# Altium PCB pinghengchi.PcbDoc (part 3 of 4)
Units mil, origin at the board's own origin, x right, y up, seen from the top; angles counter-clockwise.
Board outline 3880 x 3935 mil, 2 copper layers (Top Layer, Bottom Layer); 79 components, 147 nets, 520 pads, 52 vias.
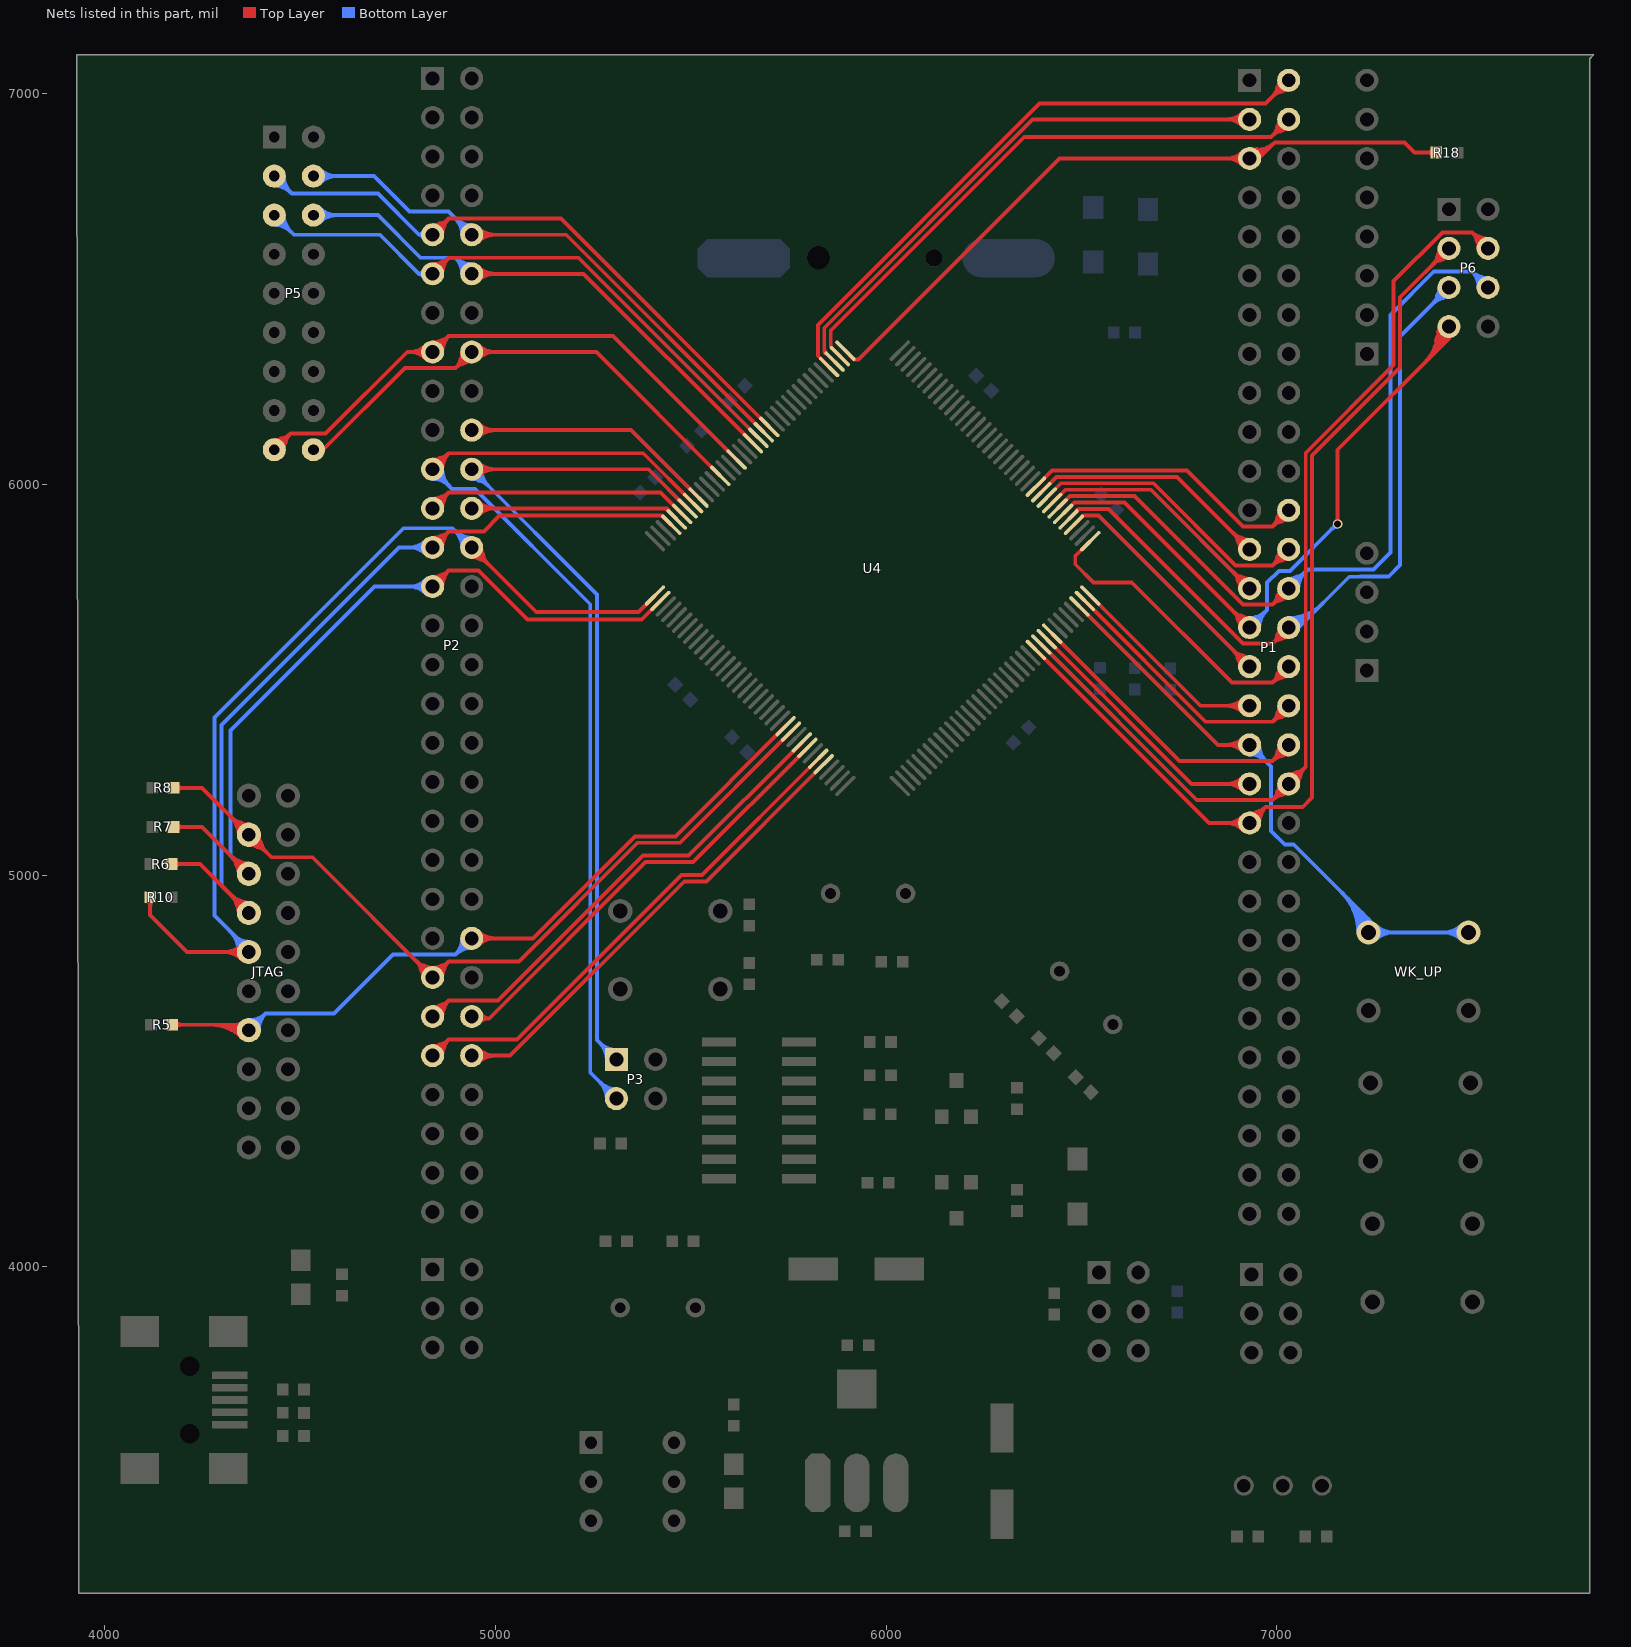
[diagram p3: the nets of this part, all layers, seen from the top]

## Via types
v1: diameter 24, hole 18, Top Layer to Bottom Layer, 42 vias
v2: diameter 24, hole 16, Top Layer to Bottom Layer, 4 vias
v3: diameter 125.98, hole 118.11, Top Layer to Bottom Layer, 4 vias
v4: diameter 30, hole 20, Top Layer to Bottom Layer, 2 vias

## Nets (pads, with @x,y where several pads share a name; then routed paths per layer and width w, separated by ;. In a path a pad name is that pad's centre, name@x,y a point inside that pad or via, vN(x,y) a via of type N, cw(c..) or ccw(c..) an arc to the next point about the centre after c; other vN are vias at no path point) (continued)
OV_RRST: P2.11 P5.5 U4.89 | length 2239.4
  Top Layer w10: P2.11@4834.67,6541.26 cw(c4872.93,6532.2) 4863.31,6570.32 ; P2.11@4840,6540 4881.03,6581.03 ; P2.11@4841.26,6534.67 ccw(c4832.2,6572.93) 4870.32,6563.31 ; U4.89@5673.33,6120.57 5212.88,6581.03 4881.03,6581.03 ; 4864.3,6564.3 ccw(c4887.9,6540.7) 4854.53,6540.21 cw(c4887.9,6540.7) 4864.3,6564.3 ; 4864.3,6564.3 cw(c4840.7,6587.9) 4840.21,6554.53 ccw(c4840.7,6587.9) 4864.3,6564.3 ; 4881.03,6581.03 ccw(c4920.87,6541.18) 4864.52,6540.36 cw(c4920.87,6541.18) 4881.03,6581.03 ; 4881.03,6581.03 cw(c4841.18,6620.87) 4840.36,6564.52 ccw(c4841.18,6620.87) 4881.03,6581.03
  Bottom Layer w10: P5.5@4435,6690 4485,6640 4705,6640 4805,6540 ; P2.11@4840,6540 4805,6540 ; 4459.8,6665.2 ccw(c4435,6640.4) 4435,6675.47 cw(c4435,6640.4) 4459.8,6665.2 ; 4459.8,6665.2 cw(c4484.6,6690) 4449.53,6690 ccw(c4484.6,6690) 4459.8,6665.2 ; 4476.87,6648.13 ccw(c4435,6606.26) 4435,6665.47 cw(c4435,6606.26) 4476.87,6648.13 ; 4476.87,6648.13 cw(c4518.74,6690) 4459.53,6690 ccw(c4518.74,6690) 4476.87,6648.13 ; 4805,6540 ccw(c4805,6552.71) 4816.94,6548.37 cw(c4805,6552.71) 4805,6540 ; 4805,6540 cw(c4805,6527.29) 4816.94,6531.63 ccw(c4805,6527.29) 4805,6540
OV_SCL: P2.10 P5.4 U4.88 | length 2312.4
  Top Layer w10: P2.10@4940,6640 5181.74,6640 U4.88@5687.25,6134.49 ; 4975.07,6640 ccw(c4975.07,6604.93) 4950.27,6629.73 cw(c4975.07,6604.93) 4975.07,6640 ; 4975.07,6640 cw(c4975.07,6675.07) 4950.27,6650.27 ccw(c4975.07,6675.07) 4975.07,6640 ; 4999.21,6640 ccw(c4999.21,6580.79) 4957.34,6622.66 cw(c4999.21,6580.79) 4999.21,6640 ; 4999.21,6640 cw(c4999.21,6699.21) 4957.34,6657.34 ccw(c4999.21,6699.21) 4999.21,6640
  Bottom Layer w10: P5.4@4535,6790 4690,6790 4781.03,6698.97 4881.03,6698.97 P2.10@4940,6640 ; 4570.07,6790 ccw(c4570.07,6754.93) 4545.27,6779.73 cw(c4570.07,6754.93) 4570.07,6790 ; 4570.07,6790 cw(c4570.07,6825.07) 4545.27,6800.27 ccw(c4570.07,6825.07) 4570.07,6790 ; 4594.21,6790 ccw(c4594.21,6730.79) 4552.34,6772.66 cw(c4594.21,6730.79) 4594.21,6790 ; 4594.21,6790 cw(c4594.21,6849.21) 4552.34,6807.34 ccw(c4594.21,6849.21) 4594.21,6790 ; 4898.13,6681.87 ccw(c4940,6723.74) 4940,6664.53 cw(c4940,6723.74) 4898.13,6681.87 ; 4898.13,6681.87 cw(c4856.26,6640) 4915.47,6640 ccw(c4856.26,6640) 4898.13,6681.87 ; 4915.2,6664.8 ccw(c4940,6689.6) 4940,6654.53 cw(c4940,6689.6) 4915.2,6664.8 ; 4915.2,6664.8 cw(c4890.4,6640) 4925.47,6640 ccw(c4890.4,6640) 4915.2,6664.8
OV_SDA: P2.12 P5.6 U4.90 | length 2245.6
  Top Layer w10: P2.12@4940,6540 5226.07,6540 U4.90@5659.41,6106.66 ; 4975.07,6540 ccw(c4975.07,6504.93) 4950.27,6529.73 cw(c4975.07,6504.93) 4975.07,6540 ; 4975.07,6540 cw(c4975.07,6575.07) 4950.27,6550.27 ccw(c4975.07,6575.07) 4975.07,6540 ; 4999.21,6540 ccw(c4999.21,6480.79) 4957.34,6522.66 cw(c4999.21,6480.79) 4999.21,6540 ; 4999.21,6540 cw(c4999.21,6599.21) 4957.34,6557.34 ccw(c4999.21,6599.21) 4999.21,6540
  Bottom Layer w10: P5.6@4535,6690 4700,6690 4808.97,6581.03 4898.97,6581.03 ; P2.12@4940,6540 4898.97,6581.03 ; 4570.07,6690 ccw(c4570.07,6654.93) 4545.27,6679.73 cw(c4570.07,6654.93) 4570.07,6690 ; 4570.07,6690 cw(c4570.07,6725.07) 4545.27,6700.27 ccw(c4570.07,6725.07) 4570.07,6690 ; 4594.21,6690 ccw(c4594.21,6630.79) 4552.34,6672.66 cw(c4594.21,6630.79) 4594.21,6690 ; 4594.21,6690 cw(c4594.21,6749.21) 4552.34,6707.34 ccw(c4594.21,6749.21) 4594.21,6690 ; 4898.97,6581.03 ccw(c4938.82,6620.87) 4939.64,6564.52 cw(c4938.82,6620.87) 4898.97,6581.03 ; 4898.97,6581.03 cw(c4859.13,6541.18) 4915.48,6540.36 ccw(c4859.13,6541.18) 4898.97,6581.03 ; 4915.7,6564.3 ccw(c4939.3,6587.9) 4939.79,6554.53 cw(c4939.3,6587.9) 4915.7,6564.3 ; 4915.7,6564.3 cw(c4892.1,6540.7) 4925.47,6540.21 ccw(c4892.1,6540.7) 4915.7,6564.3
OV_VSYNC: P2.15 P5.17 U4.93 | length 2476.2
  Top Layer w10: P5.17@4429.67,6091.26 cw(c4467.93,6082.2) 4458.31,6120.32 ; P5.17@4435,6090 4476.03,6131.03 ; P5.17@4436.26,6084.67 ccw(c4427.2,6122.93) 4465.32,6113.31 ; P2.15@4834.67,6341.26 cw(c4872.93,6332.2) 4863.31,6370.32 ; P2.15@4841.26,6334.67 ccw(c4832.2,6372.93) 4870.32,6363.31 ; U4.93@5617.65,6064.9 5301.52,6381.03 4881.03,6381.03 ; 4459.3,6114.3 ccw(c4482.9,6090.7) 4449.53,6090.21 cw(c4482.9,6090.7) 4459.3,6114.3 ; 4459.3,6114.3 cw(c4435.7,6137.9) 4435.21,6104.53 ccw(c4435.7,6137.9) 4459.3,6114.3 ; 4476.03,6131.03 ccw(c4515.87,6091.18) 4459.52,6090.36 cw(c4515.87,6091.18) 4476.03,6131.03 ; 4476.03,6131.03 cw(c4436.18,6170.87) 4435.36,6114.52 ccw(c4436.18,6170.87) 4476.03,6131.03 ; 4476.03,6131.03 4566.03,6131.03 4775,6340 P2.15@4840,6340 4881.03,6381.03 ; 4780.79,6340 ccw(c4780.79,6399.21) 4822.66,6357.34 cw(c4780.79,6399.21) 4780.79,6340 ; 4780.79,6340 cw(c4780.79,6280.79) 4822.66,6322.66 ccw(c4780.79,6280.79) 4780.79,6340 ; 4804.93,6340 ccw(c4804.93,6375.07) 4829.73,6350.27 cw(c4804.93,6375.07) 4804.93,6340 ; 4804.93,6340 cw(c4804.93,6304.93) 4829.73,6329.73 ccw(c4804.93,6304.93) 4804.93,6340 ; 4864.3,6364.3 ccw(c4887.9,6340.7) 4854.53,6340.21 cw(c4887.9,6340.7) 4864.3,6364.3 ; 4864.3,6364.3 cw(c4840.7,6387.9) 4840.21,6354.53 ccw(c4840.7,6387.9) 4864.3,6364.3 ; 4881.03,6381.03 ccw(c4920.87,6341.18) 4864.52,6340.36 cw(c4920.87,6341.18) 4881.03,6381.03 ; 4881.03,6381.03 cw(c4841.18,6420.87) 4840.36,6364.52 ccw(c4841.18,6420.87) 4881.03,6381.03
OV_WEN: P2.16 P5.18 U4.96 | length 1944.8
  Top Layer w10: P5.18@4535,6090 4560,6090 4768.97,6298.97 4898.97,6298.97 ; 4909.68,6316.69 cw(c4947.8,6307.07) P2.16@4938.74,6345.33 ; 4916.69,6309.68 ccw(c4907.07,6347.8) P2.16@4945.33,6338.74 ; U4.96@5575.89,6023.14 5259.03,6340 P2.16@4940,6340 4898.97,6298.97 ; 4898.97,6298.97 ccw(c4859.13,6338.82) 4915.48,6339.64 cw(c4859.13,6338.82) 4898.97,6298.97 ; 4898.97,6298.97 cw(c4938.82,6259.13) 4939.64,6315.48 ccw(c4938.82,6259.13) 4898.97,6298.97 ; 4915.7,6315.7 ccw(c4892.1,6339.3) 4925.47,6339.79 cw(c4892.1,6339.3) 4915.7,6315.7 ; 4915.7,6315.7 cw(c4939.3,6292.1) 4939.79,6325.47 ccw(c4939.3,6292.1) 4915.7,6315.7 ; 4975.07,6340 ccw(c4975.07,6304.93) 4950.27,6329.73 cw(c4975.07,6304.93) 4975.07,6340 ; 4975.07,6340 cw(c4975.07,6375.07) 4950.27,6350.27 ccw(c4975.07,6375.07) 4975.07,6340 ; 4999.21,6340 ccw(c4999.21,6280.79) 4957.34,6322.66 cw(c4999.21,6280.79) 4999.21,6340 ; 4999.21,6340 cw(c4999.21,6399.21) 4957.34,6357.34 ccw(c4999.21,6399.21) 4999.21,6340
OV_WRST: P2.9 P5.3 U4.87 | length 2297.2
  Top Layer w10: P2.9@4834.67,6641.26 cw(c4872.93,6632.2) 4863.31,6670.32 ; P2.9@4840,6640 4881.03,6681.03 ; P2.9@4841.26,6634.67 ccw(c4832.2,6672.93) 4870.32,6663.31 ; U4.87@5701.17,6148.41 5168.55,6681.03 4881.03,6681.03 ; 4864.3,6664.3 ccw(c4887.9,6640.7) 4854.53,6640.21 cw(c4887.9,6640.7) 4864.3,6664.3 ; 4864.3,6664.3 cw(c4840.7,6687.9) 4840.21,6654.53 ccw(c4840.7,6687.9) 4864.3,6664.3 ; 4881.03,6681.03 ccw(c4920.87,6641.18) 4864.52,6640.36 cw(c4920.87,6641.18) 4881.03,6681.03 ; 4881.03,6681.03 cw(c4841.18,6720.87) 4840.36,6664.52 ccw(c4841.18,6720.87) 4881.03,6681.03
  Bottom Layer w10: P5.3@4435,6790 4480,6745 4700,6745 4805,6640 ; P2.9@4840,6640 4805,6640 ; 4459.8,6765.2 ccw(c4435,6740.4) 4435,6775.47 cw(c4435,6740.4) 4459.8,6765.2 ; 4459.8,6765.2 cw(c4484.6,6790) 4449.53,6790 ccw(c4484.6,6790) 4459.8,6765.2 ; 4476.87,6748.13 ccw(c4435,6706.26) 4435,6765.47 cw(c4435,6706.26) 4476.87,6748.13 ; 4476.87,6748.13 cw(c4518.74,6790) 4459.53,6790 ccw(c4518.74,6790) 4476.87,6748.13 ; 4805,6640 ccw(c4805,6652.71) 4816.94,6648.37 cw(c4805,6652.71) 4805,6640 ; 4805,6640 cw(c4805,6627.29) 4816.94,6631.63 ccw(c4805,6627.29) 4805,6640
PA0: P1.35 U4.34 WK_UP.2 | length 3674.7
  Top Layer w10: U4.34@6494.57,5689.07 6848.65,5335 P1.35@6930,5335 ; 6870.79,5335 ccw(c6870.79,5394.21) 6912.66,5352.34 cw(c6870.79,5394.21) 6870.79,5335 ; 6870.79,5335 cw(c6870.79,5275.79) 6912.66,5317.66 ccw(c6870.79,5275.79) 6870.79,5335 ; 6894.93,5335 ccw(c6894.93,5370.07) 6919.73,5345.27 cw(c6894.93,5370.07) 6894.93,5335 ; 6894.93,5335 cw(c6894.93,5299.93) 6919.73,5324.73 ccw(c6894.93,5299.93) 6894.93,5335
  Bottom Layer w10: P1.35@6930,5335 6985,5280 6985,5115 7020,5080 7043.02,5080 7234.09,4888.93 ; 7201.24,4919.14 ccw(c7277.09,4939.07) WK_UP.2@7241.38,4869.24 ; 7206.92,4897.51 ccw(c7263.43,4912.36) WK_UP.2@7236.83,4860.34 ; WK_UP.2@7211.58,4868 ccw(c7174.35,4889.49) 7215.87,4900.62 ; 7217.59,4894.21 ccw(c7252.02,4903.44) WK_UP.2@7239.65,4870.01 ; WK_UP.2@7490,4855 WK_UP.2@7234.09,4855 7234.09,4888.93 ; 6954.8,5310.2 ccw(c6930,5285.4) 6930,5320.47 cw(c6930,5285.4) 6954.8,5310.2 ; 6954.8,5310.2 cw(c6979.6,5335) 6944.53,5335 ccw(c6979.6,5335) 6954.8,5310.2 ; 6971.87,5293.13 ccw(c6930,5251.26) 6930,5310.47 cw(c6930,5251.26) 6971.87,5293.13 ; 6971.87,5293.13 cw(c7013.74,5335) 6954.53,5335 ccw(c7013.74,5335) 6971.87,5293.13 ; 7234.09,4888.93 ccw(c7243.23,4888.93) 7240.85,4880.11 cw(c7243.23,4888.93) 7234.09,4888.93 ; 7234.09,4888.93 cw(c7224.96,4888.93) 7227.33,4880.11 ccw(c7224.96,4888.93) 7234.09,4888.93 ; 7272.72,4855 ccw(c7272.72,4816.37) 7245.41,4843.69 cw(c7272.72,4816.37) 7272.72,4855 ; 7272.72,4855 cw(c7272.72,4893.63) 7245.41,4866.31 ccw(c7272.72,4893.63) 7272.72,4855 ; 7296.86,4855 ccw(c7296.86,4792.23) 7252.48,4836.62 cw(c7296.86,4792.23) 7296.86,4855 ; 7296.86,4855 cw(c7296.86,4917.77) 7252.48,4873.38 ccw(c7296.86,4917.77) 7296.86,4855 ; 7427.23,4855 ccw(c7427.23,4917.77) 7471.62,4873.38 cw(c7427.23,4917.77) 7427.23,4855 ; 7427.23,4855 cw(c7427.23,4792.23) 7471.62,4836.62 ccw(c7427.23,4792.23) 7427.23,4855 ; 7451.37,4855 ccw(c7451.37,4893.63) 7478.69,4866.31 cw(c7451.37,4893.63) 7451.37,4855 ; 7451.37,4855 cw(c7451.37,4816.37) 7478.69,4843.69 ccw(c7451.37,4816.37) 7451.37,4855 ; 7165.72,4957.3 cw(c7063.42,4855) 7208.09,4855 ccw(c7063.42,4855) 7165.72,4957.3 ; 7182.79,4940.23 cw(c7097.56,4855) 7218.09,4855 ccw(c7097.56,4855) 7182.79,4940.23 ; 7199.86,4923.16 cw(c7131.7,4855) 7228.09,4855 ccw(c7131.7,4855) 7199.86,4923.16 ; 7216.93,4906.09 cw(c7165.84,4855) 7238.09,4855 ccw(c7165.84,4855) 7216.93,4906.09 ; 7234,4889.02 cw(c7199.98,4855) 7248.09,4855 ccw(c7199.98,4855) 7234,4889.02
PA1: P1.34 U4.35 | length 1039.4
  Top Layer w10: U4.35@6508.49,5702.99 6817.51,5393.97 6988.97,5393.97 ; 6999.68,5411.69 cw(c7037.8,5402.07) P1.34@7028.74,5440.33 ; 7006.69,5404.68 ccw(c6997.07,5442.8) P1.34@7035.33,5433.74 ; P1.34@7030,5435 6988.97,5393.97 ; 6988.97,5393.97 ccw(c6949.13,5433.82) 7005.48,5434.64 cw(c6949.13,5433.82) 6988.97,5393.97 ; 6988.97,5393.97 cw(c7028.82,5354.13) 7029.64,5410.48 ccw(c7028.82,5354.13) 6988.97,5393.97 ; 7005.7,5410.7 ccw(c6982.1,5434.3) 7015.47,5434.79 cw(c6982.1,5434.3) 7005.7,5410.7 ; 7005.7,5410.7 cw(c7029.3,5387.1) 7029.79,5420.47 ccw(c7029.3,5387.1) 7005.7,5410.7
PA2: P1.33 U4.36 | length 820.6
  Top Layer w10: U4.36@6522.41,5716.91 6804.32,5435 P1.33@6930,5435 ; 6870.79,5435 ccw(c6870.79,5494.21) 6912.66,5452.34 cw(c6870.79,5494.21) 6870.79,5435 ; 6870.79,5435 cw(c6870.79,5375.79) 6912.66,5417.66 ccw(c6870.79,5375.79) 6870.79,5435 ; 6894.93,5435 ccw(c6894.93,5470.07) 6919.73,5445.27 cw(c6894.93,5470.07) 6894.93,5435 ; 6894.93,5435 cw(c6894.93,5399.93) 6919.73,5424.73 ccw(c6894.93,5399.93) 6894.93,5435
PA3: P1.32 U4.37 | length 1136.4
  Top Layer w10: U4.37@6522.41,5856.11 6484,5817.69 6484,5797 6531,5750 6628.52,5750 6884.55,5493.97 6988.97,5493.97 ; 6999.68,5511.69 cw(c7037.8,5502.07) P1.32@7028.74,5540.33 ; 7006.69,5504.68 ccw(c6997.07,5542.8) P1.32@7035.33,5533.74 ; P1.32@7030,5535 6988.97,5493.97 ; 6988.97,5493.97 ccw(c6949.13,5533.82) 7005.48,5534.64 cw(c6949.13,5533.82) 6988.97,5493.97 ; 6988.97,5493.97 cw(c7028.82,5454.13) 7029.64,5510.48 ccw(c7028.82,5454.13) 6988.97,5493.97 ; 7005.7,5510.7 ccw(c6982.1,5534.3) 7015.47,5534.79 cw(c6982.1,5534.3) 7005.7,5510.7 ; 7005.7,5510.7 cw(c7029.3,5487.1) 7029.79,5520.47 ccw(c7029.3,5487.1) 7005.7,5510.7
PA4: P1.31 U4.40 | length 1012.2
  Top Layer w10: U4.40@6480.65,5897.86 6504.37,5921.58 6543.42,5921.58 P1.31@6930,5535 ; 6899.48,5557.35 ccw(c6936.61,5567.3) P1.31@6928.9,5529.64 ; 6907.65,5565.52 cw(c6897.7,5528.39) P1.31@6935.36,5536.1 ; 6888.13,5576.87 ccw(c6930,5618.74) 6930,5559.53 cw(c6930,5618.74) 6888.13,5576.87 ; 6888.13,5576.87 cw(c6846.26,5535) 6905.47,5535 ccw(c6846.26,5535) 6888.13,5576.87 ; 6905.2,5559.8 ccw(c6930,5584.6) 6930,5549.53 cw(c6930,5584.6) 6905.2,5559.8 ; 6905.2,5559.8 cw(c6880.4,5535) 6915.47,5535 ccw(c6880.4,5535) 6905.2,5559.8 ; U4.40@6501.87,5919.43 cw(c6507.07,5914.23) 6507.07,5921.58 ccw(c6507.07,5914.23) U4.40@6501.87,5919.43
PA5: P1.30 P6.5 U4.41 | length 3236.1
  Top Layer w10: U4.41@6466.74,5911.78 6493.04,5938.08 ; 6999.68,5611.69 cw(c7037.8,5602.07) P1.30@7028.74,5640.33 ; 7006.69,5604.68 ccw(c6997.07,5642.8) P1.30@7035.33,5633.74 ; P1.30@7030,5635 6988.97,5593.97 ; 6493.04,5938.08 ccw(c6493.04,5932.92) 6487.88,5933.19 cw(c6493.04,5932.92) 6493.04,5938.08 ; 6493.04,5938.08 6568.89,5938.08 6913.01,5593.97 6988.97,5593.97 ; 6988.97,5593.97 ccw(c6949.13,5633.82) 7005.48,5634.64 cw(c6949.13,5633.82) 6988.97,5593.97 ; 6988.97,5593.97 cw(c7028.82,5554.13) 7029.64,5610.48 ccw(c7028.82,5554.13) 6988.97,5593.97 ; 7005.7,5610.7 ccw(c6982.1,5634.3) 7015.47,5634.79 cw(c6982.1,5634.3) 7005.7,5610.7 ; 7005.7,5610.7 cw(c7029.3,5587.1) 7029.79,5620.47 ccw(c7029.3,5587.1) 7005.7,5610.7 ; U4.41@6487.95,5933.35 cw(c6499.38,5921.92) 6499.38,5938.08 ccw(c6499.38,5921.92) U4.41@6487.95,5933.35
  Bottom Layer w10: P1.30@7030,5635 7055,5635 7185,5765 7211.98,5765 7213.01,5766.03 7286.03,5766.03 7315,5795 7315,6380 P6.5@7440,6505 ; P1.30@7034.2,5633.3 cw(c7073.3,5617.44) 7062.38,5658.2 ; P1.30@7043.46,5629.54 cw(c7096.63,5607.98) 7081.78,5663.4 ; P1.30@7044.29,5632.4 cw(c7062.49,5629.08) 7057.7,5646.95 ; 7409.48,6482.65 cw(c7446.61,6472.7) P6.5@7438.9,6510.36 ; 7398.13,6463.13 ccw(c7356.26,6505) 7415.47,6505 cw(c7356.26,6505) 7398.13,6463.13 ; 7398.13,6463.13 cw(c7440,6421.26) 7440,6480.47 ccw(c7440,6421.26) 7398.13,6463.13 ; 7415.2,6480.2 ccw(c7390.4,6505) 7425.47,6505 cw(c7390.4,6505) 7415.2,6480.2 ; 7415.2,6480.2 cw(c7440,6455.4) 7440,6490.47 ccw(c7440,6455.4) 7415.2,6480.2 ; P1.30@7030,5629.53 ccw(c7030,5676.67) 7063.34,5643.34 cw(c7030,5676.67) P1.30@7030,5629.53 ; P1.30@7030,5639.53 ccw(c7030,5710.81) 7080.41,5660.41 cw(c7030,5710.81) P1.30@7030,5639.53 ; P1.30@7030,5649.53 ccw(c7030,5744.96) 7097.48,5677.48 cw(c7030,5744.96) P1.30@7030,5649.53 ; P1.30@7030,5659.53 ccw(c7030,5779.1) 7114.55,5694.55 cw(c7030,5779.1) P1.30@7030,5659.53
PA6: P1.29 P6.7 U4.42 | length 3356.3
  Top Layer w10: U4.42@6452.82,5925.7 6481.7,5954.58 6610.42,5954.58 P1.29@6930,5635 ; 6899.48,5657.35 ccw(c6936.61,5667.3) P1.29@6928.9,5629.64 ; 6907.65,5665.52 cw(c6897.7,5628.39) P1.29@6935.36,5636.1 ; v1(7155,5900) 7155,6090 7440,6375 ; 7401.59,6345.38 cw(c7487.44,6325.39) P6.7@7442.32,6401.11 ; 7406.92,6368.27 cw(c7470.74,6353.4) P6.7@7437.2,6409.7 ; 7410.4,6348.75 cw(c7475.16,6331.39) P6.7@7446.26,6391.89 ; 7412.25,6391.16 cw(c7454.05,6381.42) P6.7@7432.08,6418.29 ; 7416.02,6369.71 cw(c7462.85,6357.17) P6.7@7441.95,6400.91 ; P6.7@7418.76,6392.74 cw(c7380.41,6370.59) 7423.18,6359.13 ; 7426.99,6373.35 cw(c7451.52,6366.78) P6.7@7444.19,6391.09 ; P6.7@7440,6405 7440,6375 ; 6888.13,5676.87 ccw(c6930,5718.74) 6930,5659.53 cw(c6930,5718.74) 6888.13,5676.87 ; 6888.13,5676.87 cw(c6846.26,5635) 6905.47,5635 ccw(c6846.26,5635) 6888.13,5676.87 ; 6905.2,5659.8 ccw(c6930,5684.6) 6930,5649.53 cw(c6930,5684.6) 6905.2,5659.8 ; 6905.2,5659.8 cw(c6880.4,5635) 6915.47,5635 ccw(c6880.4,5635) 6905.2,5659.8 ; 7155,5916.9 ccw(c7171.9,5916.9) 7159.95,5904.95 cw(c7171.9,5916.9) 7155,5916.9 ; 7155,5916.9 cw(c7138.1,5916.9) 7150.05,5904.95 ccw(c7138.1,5916.9) 7155,5916.9 ; 7440,6375 ccw(c7433.92,6375) 7435.13,6380.96 cw(c7433.92,6375) 7440,6375 ; 7440,6375 cw(c7446.08,6375) 7444.87,6380.96 ccw(c7446.08,6375) 7440,6375 ; 7376.92,6311.92 ccw(c7283.83,6405) 7415.47,6405 cw(c7283.83,6405) 7376.92,6311.92 ; 7393.99,6328.99 ccw(c7317.97,6405) 7425.47,6405 cw(c7317.97,6405) 7393.99,6328.99 ; 7411.06,6346.06 ccw(c7352.12,6405) 7435.47,6405 cw(c7352.12,6405) 7411.06,6346.06 ; 7428.13,6363.13 ccw(c7386.26,6405) 7445.47,6405 cw(c7386.26,6405) 7428.13,6363.13
  Bottom Layer w10: P1.29@6930,5635 6975,5680 6975,5750 7005,5780 7033.02,5780 v1@7155,5901.98 ; 6954.8,5659.8 ccw(c6979.6,5635) 6944.53,5635 cw(c6979.6,5635) 6954.8,5659.8 ; 6954.8,5659.8 cw(c6930,5684.6) 6930,5649.53 ccw(c6930,5684.6) 6954.8,5659.8 ; 6971.87,5676.87 ccw(c7013.74,5635) 6954.53,5635 cw(c7013.74,5635) 6971.87,5676.87 ; 6971.87,5676.87 cw(c6930,5718.74) 6930,5659.53 ccw(c6930,5718.74) 6971.87,5676.87 ; 7139.67,5886.65 cw(c7155,5871.32) 7155,5893 ccw(c7155,5871.32) 7139.67,5886.65 ; 7144.45,5891.43 ccw(c7135.88,5900) 7148,5900 cw(c7135.88,5900) 7144.45,5891.43
PA7: P1.28 P6.6 U4.43 | length 2953.8
  Top Layer w10: U4.43@6438.9,5939.62 6470.36,5971.08 6635.89,5971.08 6913.01,5693.97 6988.97,5693.97 ; 6999.68,5711.69 cw(c7037.8,5702.07) P1.28@7028.74,5740.33 ; 7006.69,5704.68 ccw(c6997.07,5742.8) P1.28@7035.33,5733.74 ; P1.28@7030,5735 6988.97,5693.97 ; 6988.97,5693.97 ccw(c6949.13,5733.82) 7005.48,5734.64 cw(c6949.13,5733.82) 6988.97,5693.97 ; 6988.97,5693.97 cw(c7028.82,5654.13) 7029.64,5710.48 ccw(c7028.82,5654.13) 6988.97,5693.97 ; 7005.7,5710.7 ccw(c6982.1,5734.3) 7015.47,5734.79 cw(c6982.1,5734.3) 7005.7,5710.7 ; 7005.7,5710.7 cw(c7029.3,5687.1) 7029.79,5720.47 ccw(c7029.3,5687.1) 7005.7,5710.7
  Bottom Layer w10: P1.28@7024.64,5736.1 cw(c7062.3,5728.39) 7052.35,5765.52 ; P1.28@7030,5735 7078.97,5783.97 7246.99,5783.97 7290,5826.98 7290,6435 7401.03,6546.03 7498.97,6546.03 ; P6.6@7540,6505 7498.97,6546.03 ; 7054.8,5759.8 ccw(c7079.6,5735) 7044.53,5735 cw(c7079.6,5735) 7054.8,5759.8 ; 7054.8,5759.8 cw(c7030,5784.6) 7030,5749.53 ccw(c7030,5784.6) 7054.8,5759.8 ; 7071.87,5776.87 ccw(c7113.74,5735) 7054.53,5735 cw(c7113.74,5735) 7071.87,5776.87 ; 7071.87,5776.87 cw(c7030,5818.74) 7030,5759.53 ccw(c7030,5818.74) 7071.87,5776.87 ; 7498.97,6546.03 ccw(c7538.82,6585.87) 7539.64,6529.52 cw(c7538.82,6585.87) 7498.97,6546.03 ; 7498.97,6546.03 cw(c7459.13,6506.18) 7515.48,6505.36 ccw(c7459.13,6506.18) 7498.97,6546.03 ; 7515.7,6529.3 ccw(c7539.3,6552.9) 7539.79,6519.53 cw(c7539.3,6552.9) 7515.7,6529.3 ; 7515.7,6529.3 cw(c7492.1,6505.7) 7525.47,6505.21 ccw(c7492.1,6505.7) 7515.7,6529.3
PA8: P2.20 U4.100 | length 947.9
  Top Layer w10: P2.20@4940,6140 5347.68,6140 U4.100@5520.22,5967.46 ; 4975.07,6140 ccw(c4975.07,6104.93) 4950.27,6129.73 cw(c4975.07,6104.93) 4975.07,6140 ; 4975.07,6140 cw(c4975.07,6175.07) 4950.27,6150.27 ccw(c4975.07,6175.07) 4975.07,6140 ; 4999.21,6140 ccw(c4999.21,6080.79) 4957.34,6122.66 cw(c4999.21,6080.79) 4999.21,6140 ; 4999.21,6140 cw(c4999.21,6199.21) 4957.34,6157.34 ccw(c4999.21,6199.21) 4999.21,6140
PA9: P2.21 P3.3 U4.101 | length 3540.1
  Top Layer w10: P2.21@4834.67,6041.26 cw(c4872.93,6032.2) 4863.31,6070.32 ; P2.21@4840,6040 4881.03,6081.03 ; P2.21@4841.26,6034.67 ccw(c4832.2,6072.93) 4870.32,6063.31 ; U4.101@5506.3,5953.54 5378.81,6081.03 4881.03,6081.03 ; 4864.3,6064.3 ccw(c4887.9,6040.7) 4854.53,6040.21 cw(c4887.9,6040.7) 4864.3,6064.3 ; 4864.3,6064.3 cw(c4840.7,6087.9) 4840.21,6054.53 ccw(c4840.7,6087.9) 4864.3,6064.3 ; 4881.03,6081.03 ccw(c4920.87,6041.18) 4864.52,6040.36 cw(c4920.87,6041.18) 4881.03,6081.03 ; 4881.03,6081.03 cw(c4841.18,6120.87) 4840.36,6064.52 ccw(c4841.18,6120.87) 4881.03,6081.03
  Bottom Layer w10: P2.21@4840,6040 4890,5990 4948.02,5990 5243.33,5694.69 5243.33,4496.67 P3.3@5310,4430 ; 4864.8,6015.2 ccw(c4840,5990.4) 4840,6025.47 cw(c4840,5990.4) 4864.8,6015.2 ; 4864.8,6015.2 cw(c4889.6,6040) 4854.53,6040 ccw(c4889.6,6040) 4864.8,6015.2 ; 4881.87,5998.13 ccw(c4840,5956.26) 4840,6015.47 cw(c4840,5956.26) 4881.87,5998.13 ; 4881.87,5998.13 cw(c4923.74,6040) 4864.53,6040 ccw(c4923.74,6040) 4881.87,5998.13 ; 5268.13,4471.87 ccw(c5310,4513.74) 5310,4454.53 cw(c5310,4513.74) 5268.13,4471.87 ; 5268.13,4471.87 cw(c5226.26,4430) 5285.47,4430 ccw(c5226.26,4430) 5268.13,4471.87 ; 5285.2,4454.8 ccw(c5310,4479.6) 5310,4444.53 cw(c5310,4479.6) 5285.2,4454.8 ; 5285.2,4454.8 cw(c5260.4,4430) 5295.47,4430 ccw(c5260.4,4430) 5285.2,4454.8
PA10: P2.22 P3.1 U4.102 | length 3188.4
  Top Layer w10: P2.22@4940,6040 5392,6040 U4.102@5492.38,5939.62 ; 4975.07,6040 ccw(c4975.07,6004.93) 4950.27,6029.73 cw(c4975.07,6004.93) 4975.07,6040 ; 4975.07,6040 cw(c4975.07,6075.07) 4950.27,6050.27 ccw(c4975.07,6075.07) 4975.07,6040 ; 4999.21,6040 ccw(c4999.21,5980.79) 4957.34,6022.66 cw(c4999.21,5980.79) 4999.21,6040 ; 4999.21,6040 cw(c4999.21,6099.21) 4957.34,6057.34 ccw(c4999.21,6099.21) 4999.21,6040
  Bottom Layer w10: P2.22@4934.64,6038.9 ccw(c4972.3,6046.61) 4962.35,6009.48 ; P2.22@4940,6040 5260,5720 5260,4580 P3.1@5310,4530 ; 4964.8,6015.2 ccw(c4940,5990.4) 4940,6025.47 cw(c4940,5990.4) 4964.8,6015.2 ; 4964.8,6015.2 cw(c4989.6,6040) 4954.53,6040 ccw(c4989.6,6040) 4964.8,6015.2 ; 4981.87,5998.13 ccw(c4940,5956.26) 4940,6015.47 cw(c4940,5956.26) 4981.87,5998.13 ; 4981.87,5998.13 cw(c5023.74,6040) 4964.53,6040 ccw(c5023.74,6040) 4981.87,5998.13 ; 5268.13,4571.87 ccw(c5310,4613.74) 5310,4554.53 cw(c5310,4613.74) 5268.13,4571.87 ; 5268.13,4571.87 cw(c5226.26,4530) 5285.47,4530 ccw(c5226.26,4530) 5268.13,4571.87 ; P3.1@5285.2,4554.8 ccw(c5310,4579.6) 5310,4544.53 cw(c5310,4579.6) P3.1@5285.2,4554.8 ; P3.1@5285.2,4554.8 cw(c5260.4,4530) 5295.47,4530 ccw(c5260.4,4530) P3.1@5285.2,4554.8
PA11: P2.23 U4.103 | length 1051.3
  Top Layer w10: P2.23@4834.67,5941.26 cw(c4872.93,5932.2) 4863.31,5970.32 ; P2.23@4840,5940 4881.03,5981.03 ; P2.23@4841.26,5934.67 ccw(c4832.2,5972.93) 4870.32,5963.31 ; U4.103@5478.46,5925.7 5423.13,5981.03 4881.03,5981.03 ; 4864.3,5964.3 ccw(c4887.9,5940.7) 4854.53,5940.21 cw(c4887.9,5940.7) 4864.3,5964.3 ; 4864.3,5964.3 cw(c4840.7,5987.9) 4840.21,5954.53 ccw(c4840.7,5987.9) 4864.3,5964.3 ; 4881.03,5981.03 ccw(c4920.87,5941.18) 4864.52,5940.36 cw(c4920.87,5941.18) 4881.03,5981.03 ; 4881.03,5981.03 cw(c4841.18,6020.87) 4840.36,5964.52 ccw(c4841.18,6020.87) 4881.03,5981.03
PA12: P2.24 U4.104 | length 889.8
  Top Layer w10: P2.24@4940,5940 5436.32,5940 ; U4.104@5464.54,5911.78 5436.32,5940 ; 4975.07,5940 ccw(c4975.07,5904.93) 4950.27,5929.73 cw(c4975.07,5904.93) 4975.07,5940 ; 4975.07,5940 cw(c4975.07,5975.07) 4950.27,5950.27 ccw(c4975.07,5975.07) 4975.07,5940 ; 4999.21,5940 ccw(c4999.21,5880.79) 4957.34,5922.66 cw(c4999.21,5880.79) 4999.21,5940 ; 4999.21,5940 cw(c4999.21,5999.21) 4957.34,5957.34 ccw(c4999.21,5999.21) 4999.21,5940 ; 5436.32,5940 cw(c5436.32,5932.92) 5443.4,5933.18 ccw(c5436.32,5932.92) 5436.32,5940 ; 5427.27,5940 cw(c5427.27,5917.3) 5443.32,5933.35 ccw(c5427.27,5917.3) 5427.27,5940
PA13: JTAG.7 P2.25 R6.1 U4.105 | length 3673.9
  Top Layer w10: R6.1@4172,5030 4245,5030 JTAG.7@4370,4905 ; 4336.9,4931.5 ccw(c4377.66,4942.43) JTAG.7@4369.2,4901.08 ; 4343.5,4938.1 cw(c4332.57,4897.34) JTAG.7@4373.92,4905.8 ; P2.25@4823.5,5835 4840,5818.5 P2.25@4840,5840 4881.03,5881.03 ; P2.25@4834.67,5841.26 cw(c4872.93,5832.2) 4863.31,5870.32 ; P2.25@4841.26,5834.67 ccw(c4832.2,5872.93) 4870.32,5863.31 ; U4.105@5450.62,5897.86 5426.9,5921.58 5011.58,5921.58 4971.03,5881.03 4881.03,5881.03 ; 4196.14,5030 ccw(c4196.14,5005.86) 4179.07,5022.93 cw(c4196.14,5005.86) 4196.14,5030 ; 4196.14,5030 cw(c4196.14,5054.14) 4179.07,5037.07 ccw(c4196.14,5054.14) 4196.14,5030 ; 4325.62,4949.38 ccw(c4370,4993.77) 4370,4931 cw(c4370,4993.77) 4325.62,4949.38 ; 4325.62,4949.38 cw(c4281.23,4905) 4344,4905 ccw(c4281.23,4905) 4325.62,4949.38 ; 4342.69,4932.31 ccw(c4370,4959.63) 4370,4921 cw(c4370,4959.63) 4342.69,4932.31 ; 4342.69,4932.31 cw(c4315.37,4905) 4354,4905 ccw(c4315.37,4905) 4342.69,4932.31 ; 4864.3,5864.3 ccw(c4887.9,5840.7) 4854.53,5840.21 cw(c4887.9,5840.7) 4864.3,5864.3 ; 4864.3,5864.3 cw(c4840.7,5887.9) 4840.21,5854.53 ccw(c4840.7,5887.9) 4864.3,5864.3 ; 4881.03,5881.03 ccw(c4920.87,5841.18) 4864.52,5840.36 cw(c4920.87,5841.18) 4881.03,5881.03 ; 4881.03,5881.03 cw(c4841.18,5920.87) 4840.36,5864.52 ccw(c4841.18,5920.87) 4881.03,5881.03 ; 5424.21,5921.58 cw(c5424.21,5914.23) 5429.4,5919.43 ccw(c5424.21,5914.23) 5424.21,5921.58
  Bottom Layer w10: JTAG.7@4370,4905 4300,4975 4300,5386 4754,5840 P2.25@4840,5840 ; 4325.62,4949.38 ccw(c4370,4993.77) 4370,4931 cw(c4370,4993.77) 4325.62,4949.38 ; 4325.62,4949.38 cw(c4281.23,4905) 4344,4905 ccw(c4281.23,4905) 4325.62,4949.38 ; 4342.69,4932.31 ccw(c4370,4959.63) 4370,4921 cw(c4370,4959.63) 4342.69,4932.31 ; 4342.69,4932.31 cw(c4315.37,4905) 4354,4905 ccw(c4315.37,4905) 4342.69,4932.31 ; 4780.79,5840 ccw(c4780.79,5899.21) 4822.66,5857.34 cw(c4780.79,5899.21) 4780.79,5840 ; 4780.79,5840 cw(c4780.79,5780.79) 4822.66,5822.66 ccw(c4780.79,5780.79) 4780.79,5840 ; 4804.93,5840 ccw(c4804.93,5875.07) 4829.73,5850.27 cw(c4804.93,5875.07) 4804.93,5840 ; 4804.93,5840 cw(c4804.93,5804.93) 4829.73,5829.73 ccw(c4804.93,5804.93) 4804.93,5840
PA14: JTAG.9 P2.26 R10.2 U4.109 | length 3755.8
  Top Layer w10: R10.2@4117.5,4945.06 4117.5,4899.5 4212,4805 JTAG.9@4370,4805 ; P2.26@4934.64,5838.9 ccw(c4972.3,5846.61) 4962.35,5809.48 ; P2.26@4940,5840 5105,5675 5366.95,5675 U4.109@5408.86,5716.91 ; P2.26@4941.1,5845.36 cw(c4933.39,5807.7) 4970.52,5817.65 ; 4117.5,4920.92 ccw(c4093.36,4920.92) 4110.43,4937.99 cw(c4093.36,4920.92) 4117.5,4920.92 ; 4117.5,4920.92 cw(c4141.64,4920.92) 4124.57,4937.99 ccw(c4141.64,4920.92) 4117.5,4920.92 ; 4307.23,4805 ccw(c4307.23,4867.77) 4351.62,4823.38 cw(c4307.23,4867.77) 4307.23,4805 ; 4307.23,4805 cw(c4307.23,4742.23) 4351.62,4786.62 ccw(c4307.23,4742.23) 4307.23,4805 ; 4331.37,4805 ccw(c4331.37,4843.63) 4358.69,4816.31 cw(c4331.37,4843.63) 4331.37,4805 ; 4331.37,4805 cw(c4331.37,4766.37) 4358.69,4793.69 ccw(c4331.37,4766.37) 4331.37,4805 ; 4964.8,5815.2 ccw(c4940,5790.4) 4940,5825.47 cw(c4940,5790.4) 4964.8,5815.2 ; 4964.8,5815.2 cw(c4989.6,5840) 4954.53,5840 ccw(c4989.6,5840) 4964.8,5815.2 ; 4981.87,5798.13 ccw(c4940,5756.26) 4940,5815.47 cw(c4940,5756.26) 4981.87,5798.13 ; 4981.87,5798.13 cw(c5023.74,5840) 4964.53,5840 ccw(c5023.74,5840) 4981.87,5798.13
  Bottom Layer w10: JTAG.9@4370,4805 4370,4810 4282,4898 4282,5405 4766,5889 4891,5889 P2.26@4940,5840 ; 4898.13,5881.87 ccw(c4940,5923.74) 4940,5864.53 cw(c4940,5923.74) 4898.13,5881.87 ; 4898.13,5881.87 cw(c4856.26,5840) 4915.47,5840 ccw(c4856.26,5840) 4898.13,5881.87 ; 4915.2,5864.8 ccw(c4940,5889.6) 4940,5854.53 cw(c4940,5889.6) 4915.2,5864.8 ; 4915.2,5864.8 cw(c4890.4,5840) 4925.47,5840 ccw(c4890.4,5840) 4915.2,5864.8 ; 4322.08,4857.92 cw(c4269.16,4805) 4344,4805 ccw(c4269.16,4805) 4322.08,4857.92 ; 4334.15,4845.85 ccw(c4370,4881.7) 4370,4831 cw(c4370,4881.7) 4334.15,4845.85 ; 4339.15,4840.85 cw(c4303.3,4805) 4354,4805 ccw(c4303.3,4805) 4339.15,4840.85
PA15: JTAG.5 P2.27 R7.1 U4.110 | length 3446.5
  Top Layer w10: R7.1@4176.3,5125 R7.1@4177,5125 4250,5125 JTAG.5@4370,5005 ; 4336.9,5031.5 ccw(c4377.66,5042.43) JTAG.5@4369.2,5001.08 ; 4343.5,5038.1 cw(c4332.57,4997.34) JTAG.5@4373.92,5005.8 ; P2.27@4834.67,5741.26 cw(c4872.93,5732.2) 4863.31,5770.32 ; P2.27@4840,5740 4881.03,5781.03 ; P2.27@4841.26,5734.67 ccw(c4832.2,5772.93) 4870.32,5763.31 ; U4.110@5422.78,5702.99 5375,5655.21 5082.81,5655.21 4956.99,5781.03 4881.03,5781.03 ; 4201.14,5125 ccw(c4201.14,5100.86) 4184.07,5117.93 cw(c4201.14,5100.86) 4201.14,5125 ; 4201.14,5125 cw(c4201.14,5149.14) 4184.07,5132.07 ccw(c4201.14,5149.14) 4201.14,5125 ; 4325.62,5049.38 ccw(c4370,5093.77) 4370,5031 cw(c4370,5093.77) 4325.62,5049.38 ; 4325.62,5049.38 cw(c4281.23,5005) 4344,5005 ccw(c4281.23,5005) 4325.62,5049.38 ; 4342.69,5032.31 ccw(c4370,5059.63) 4370,5021 cw(c4370,5059.63) 4342.69,5032.31 ; 4342.69,5032.31 cw(c4315.37,5005) 4354,5005 ccw(c4315.37,5005) 4342.69,5032.31 ; 4864.3,5764.3 ccw(c4887.9,5740.7) 4854.53,5740.21 cw(c4887.9,5740.7) 4864.3,5764.3 ; 4864.3,5764.3 cw(c4840.7,5787.9) 4840.21,5754.53 ccw(c4840.7,5787.9) 4864.3,5764.3 ; 4881.03,5781.03 ccw(c4920.87,5741.18) 4864.52,5740.36 cw(c4920.87,5741.18) 4881.03,5781.03 ; 4881.03,5781.03 cw(c4841.18,5820.87) 4840.36,5764.52 ccw(c4841.18,5820.87) 4881.03,5781.03
  Bottom Layer w10: JTAG.5@4370,5005 4323,5052 4323,5372 4691,5740 P2.27@4840,5740 ; 4325.62,5049.38 ccw(c4370,5093.77) 4370,5031 cw(c4370,5093.77) 4325.62,5049.38 ; 4325.62,5049.38 cw(c4281.23,5005) 4344,5005 ccw(c4281.23,5005) 4325.62,5049.38 ; 4342.69,5032.31 ccw(c4370,5059.63) 4370,5021 cw(c4370,5059.63) 4342.69,5032.31 ; 4342.69,5032.31 cw(c4315.37,5005) 4354,5005 ccw(c4315.37,5005) 4342.69,5032.31 ; 4780.79,5740 ccw(c4780.79,5799.21) 4822.66,5757.34 cw(c4780.79,5799.21) 4780.79,5740 ; 4780.79,5740 cw(c4780.79,5680.79) 4822.66,5722.66 ccw(c4780.79,5680.79) 4780.79,5740 ; 4804.93,5740 ccw(c4804.93,5775.07) 4829.73,5750.27 cw(c4804.93,5775.07) 4804.93,5740 ; 4804.93,5740 cw(c4804.93,5704.93) 4829.73,5729.73 ccw(c4804.93,5704.93) 4804.93,5740
PB0: P1.25 U4.46 | length 1007.3
  Top Layer w10: U4.46@6397.14,5981.38 6436.34,6020.58 6744.42,6020.58 P1.25@6930,5835 ; 6899.48,5857.35 ccw(c6936.61,5867.3) P1.25@6928.9,5829.64 ; 6907.65,5865.52 cw(c6897.7,5828.39) P1.25@6935.36,5836.1 ; 6888.13,5876.87 ccw(c6930,5918.74) 6930,5859.53 cw(c6930,5918.74) 6888.13,5876.87 ; 6888.13,5876.87 cw(c6846.26,5835) 6905.47,5835 ccw(c6846.26,5835) 6888.13,5876.87 ; 6905.2,5859.8 ccw(c6930,5884.6) 6930,5849.53 cw(c6930,5884.6) 6905.2,5859.8 ; 6905.2,5859.8 cw(c6880.4,5835) 6915.47,5835 ccw(c6880.4,5835) 6905.2,5859.8
PB1: P1.24 U4.47 | length 1113.3
  Top Layer w10: U4.47@6383.22,5995.3 6425,6037.08 6769.89,6037.08 6913.01,5893.97 6988.97,5893.97 ; 6999.68,5911.69 cw(c7037.8,5902.07) P1.24@7028.74,5940.33 ; 7006.69,5904.68 ccw(c6997.07,5942.8) P1.24@7035.33,5933.74 ; P1.24@7030,5935 6988.97,5893.97 ; 6988.97,5893.97 ccw(c6949.13,5933.82) 7005.48,5934.64 cw(c6949.13,5933.82) 6988.97,5893.97 ; 6988.97,5893.97 cw(c7028.82,5854.13) 7029.64,5910.48 ccw(c7028.82,5854.13) 6988.97,5893.97 ; 7005.7,5910.7 ccw(c6982.1,5934.3) 7015.47,5934.79 cw(c6982.1,5934.3) 7005.7,5910.7 ; 7005.7,5910.7 cw(c7029.3,5887.1) 7029.79,5920.47 ccw(c7029.3,5887.1) 7005.7,5910.7
PB3: JTAG.13 P2.46 R5.1 U4.133 | length 3284.8
  Top Layer w10: R5.1@4174,4619 4356,4619 JTAG.13@4370,4605 ; P2.46@4940,4840 5096.56,4840 5357.56,5101 5461.08,5101 U4.133@5742.93,5382.85 ; 4198.14,4619 ccw(c4198.14,4594.86) 4181.07,4611.93 cw(c4198.14,4594.86) 4198.14,4619 ; 4198.14,4619 cw(c4198.14,4643.14) 4181.07,4626.07 ccw(c4198.14,4643.14) 4198.14,4619 ; 4975.07,4840 ccw(c4975.07,4804.93) 4950.27,4829.73 cw(c4975.07,4804.93) 4975.07,4840 ; 4975.07,4840 cw(c4975.07,4875.07) 4950.27,4850.27 ccw(c4975.07,4875.07) 4975.07,4840 ; 4999.21,4840 ccw(c4999.21,4780.79) 4957.34,4822.66 cw(c4999.21,4780.79) 4999.21,4840 ; 4999.21,4840 cw(c4999.21,4899.21) 4957.34,4857.34 ccw(c4999.21,4899.21) 4999.21,4840 ; 4273.43,4619 cw(c4273.43,4508.43) 4351.62,4586.62 ccw(c4273.43,4508.43) 4273.43,4619 ; 4297.57,4619 cw(c4297.57,4532.57) 4358.69,4593.69 ccw(c4297.57,4532.57) 4297.57,4619 ; 4321.72,4619 cw(c4321.72,4556.72) 4365.76,4600.76 ccw(c4321.72,4556.72) 4321.72,4619 ; 4341.03,4619 ccw(c4341.03,4633.97) 4351.62,4623.38 cw(c4341.03,4633.97) 4341.03,4619
  Bottom Layer w10: JTAG.13@4370,4605 4412.5,4647.5 ; P2.46@4940,4840 4898.97,4798.97 ; 4396.15,4631.15 ccw(c4420.72,4606.58) 4385.99,4605.5 cw(c4420.72,4606.58) 4396.15,4631.15 ; 4396.15,4631.15 cw(c4371.58,4655.72) 4370.5,4620.99 ccw(c4371.58,4655.72) 4396.15,4631.15 ; 4412.5,4647.5 ccw(c4452.42,4607.57) 4395.99,4605.81 cw(c4452.42,4607.57) 4412.5,4647.5 ; 4412.5,4647.5 cw(c4372.57,4687.42) 4370.81,4630.99 ccw(c4372.57,4687.42) 4412.5,4647.5 ; 4412.5,4647.5 4587.5,4647.5 4738.97,4798.97 4898.97,4798.97 ; 4898.97,4798.97 ccw(c4859.13,4838.82) 4915.48,4839.64 cw(c4859.13,4838.82) 4898.97,4798.97 ; 4898.97,4798.97 cw(c4938.82,4759.13) 4939.64,4815.48 ccw(c4938.82,4759.13) 4898.97,4798.97 ; 4915.7,4815.7 ccw(c4892.1,4839.3) 4925.47,4839.79 cw(c4892.1,4839.3) 4915.7,4815.7 ; 4915.7,4815.7 cw(c4939.3,4792.1) 4939.79,4825.47 ccw(c4939.3,4792.1) 4915.7,4815.7
PB4: JTAG.3 P2.47 R8.1 U4.134 | length 3695.3
  Top Layer w10: R8.1@4177,5225 4250,5225 JTAG.3@4370,5105 4427.5,5047.5 4532.5,5047.5 P2.47@4840,4740 4881.03,4781.03 ; 4336.9,5131.5 ccw(c4377.66,5142.43) JTAG.3@4369.2,5101.08 ; 4343.5,5138.1 cw(c4332.57,5097.34) JTAG.3@4373.92,5105.8 ; JTAG.3@4366.08,5104.2 ccw(c4407.43,5112.66) 4396.5,5071.9 ; JTAG.3@4370.8,5108.92 cw(c4362.34,5067.57) 4403.1,5078.5 ; 4809.48,4762.35 ccw(c4846.61,4772.3) P2.47@4838.9,4734.64 ; 4817.65,4770.52 cw(c4807.7,4733.39) P2.47@4845.36,4741.1 ; P2.47@4834.67,4741.26 cw(c4872.93,4732.2) 4863.31,4770.32 ; P2.47@4841.26,4734.67 ccw(c4832.2,4772.93) 4870.32,4763.31 ; U4.134@5756.85,5368.93 5472.42,5084.5 5364.39,5084.5 5060.92,4781.03 4881.03,4781.03 ; 4201.14,5225 ccw(c4201.14,5200.86) 4184.07,5217.93 cw(c4201.14,5200.86) 4201.14,5225 ; 4201.14,5225 cw(c4201.14,5249.14) 4184.07,5232.07 ccw(c4201.14,5249.14) 4201.14,5225 ; 4325.62,5149.38 ccw(c4370,5193.77) 4370,5131 cw(c4370,5193.77) 4325.62,5149.38 ; 4325.62,5149.38 cw(c4281.23,5105) 4344,5105 ccw(c4281.23,5105) 4325.62,5149.38 ; 4342.69,5132.31 ccw(c4370,5159.63) 4370,5121 cw(c4370,5159.63) 4342.69,5132.31 ; 4342.69,5132.31 cw(c4315.37,5105) 4354,5105 ccw(c4315.37,5105) 4342.69,5132.31 ; 4397.31,5077.69 ccw(c4370,5050.37) 4370,5089 cw(c4370,5050.37) 4397.31,5077.69 ; 4397.31,5077.69 cw(c4424.63,5105) 4386,5105 ccw(c4424.63,5105) 4397.31,5077.69 ; 4414.38,5060.62 ccw(c4370,5016.23) 4370,5079 cw(c4370,5016.23) 4414.38,5060.62 ; 4414.38,5060.62 cw(c4458.77,5105) 4396,5105 ccw(c4458.77,5105) 4414.38,5060.62 ; 4798.13,4781.87 ccw(c4840,4823.74) 4840,4764.53 cw(c4840,4823.74) 4798.13,4781.87 ; 4798.13,4781.87 cw(c4756.26,4740) 4815.47,4740 ccw(c4756.26,4740) 4798.13,4781.87 ; 4815.2,4764.8 ccw(c4840,4789.6) 4840,4754.53 cw(c4840,4789.6) 4815.2,4764.8 ; 4815.2,4764.8 cw(c4790.4,4740) 4825.47,4740 ccw(c4790.4,4740) 4815.2,4764.8 ; 4864.3,4764.3 ccw(c4887.9,4740.7) 4854.53,4740.21 cw(c4887.9,4740.7) 4864.3,4764.3 ; 4864.3,4764.3 cw(c4840.7,4787.9) 4840.21,4754.53 ccw(c4840.7,4787.9) 4864.3,4764.3 ; 4881.03,4781.03 ccw(c4920.87,4741.18) 4864.52,4740.36 cw(c4920.87,4741.18) 4881.03,4781.03 ; 4881.03,4781.03 cw(c4841.18,4820.87) 4840.36,4764.52 ccw(c4841.18,4820.87) 4881.03,4781.03
PB6: P2.49 U4.136 | length 1608
  Top Layer w10: P2.49@4834.67,4641.26 cw(c4872.93,4632.2) 4863.31,4670.32 ; P2.49@4840,4640 4881.03,4681.03 ; P2.49@4841.26,4634.67 ccw(c4832.2,4672.93) 4870.32,4663.31 ; U4.136@5784.68,5341.09 5495.1,5051.5 5378.06,5051.5 5007.59,4681.03 4881.03,4681.03 ; 4864.3,4664.3 ccw(c4887.9,4640.7) 4854.53,4640.21 cw(c4887.9,4640.7) 4864.3,4664.3 ; 4864.3,4664.3 cw(c4840.7,4687.9) 4840.21,4654.53 ccw(c4840.7,4687.9) 4864.3,4664.3 ; 4881.03,4681.03 ccw(c4920.87,4641.18) 4864.52,4640.36 cw(c4920.87,4641.18) 4881.03,4681.03 ; 4881.03,4681.03 cw(c4841.18,4720.87) 4840.36,4664.52 ccw(c4841.18,4720.87) 4881.03,4681.03
PB7: P2.50 U4.137 | length 1306
  Top Layer w10: P2.50@4940,4640 4945,4635 4984.9,4635 ; U4.137@5798.6,5327.17 5506.44,5035 5384.9,5035 4984.9,4635 ; 4984.89,4635 ccw(c4984.89,4598.16) 4957.94,4623.28 cw(c4984.89,4598.16) 4984.89,4635 ; 4984.89,4635 cw(c4984.89,4659.37) 4962.52,4649.71 ccw(c4984.89,4659.37) 4984.89,4635 ; P2.50@4953.34,4645.75 ccw(c4969.69,4652.81) 4969.69,4635 cw(c4969.69,4652.81) P2.50@4953.34,4645.75
PB8: P2.51 U4.139 | length 1673.8
  Top Layer w10: P2.51@4834.65,4541.26 cw(c4872.79,4532.29) 4863.17,4570.28 ; P2.51@4840,4540 4881.03,4581.03 ; P2.51@4841.26,4534.65 ccw(c4832.29,4572.79) 4870.28,4563.17 ; U4.139@5826.44,5299.33 5529.11,5002 5477,5002 5056.02,4581.03 4881.03,4581.03 ; 4864.28,4564.28 ccw(c4887.9,4540.66) 4854.5,4540.2 cw(c4887.9,4540.66) 4864.28,4564.28 ; 4864.28,4564.28 cw(c4840.66,4587.9) 4840.2,4554.5 ccw(c4840.66,4587.9) 4864.28,4564.28 ; 4881.03,4581.03 ccw(c4920.94,4541.11) 4864.5,4540.34 cw(c4920.94,4541.11) 4881.03,4581.03 ; 4881.03,4581.03 cw(c4841.11,4620.94) 4840.34,4564.5 ccw(c4841.11,4620.94) 4881.03,4581.03
PB9: P2.52 U4.140 | length 1505.3
  Top Layer w10: P2.52@4940,4540 5038.33,4540 5483.83,4985.5 5540.45,4985.5 U4.140@5840.36,5285.41 ; 4975.07,4540 ccw(c4975.07,4504.93) 4950.27,4529.73 cw(c4975.07,4504.93) 4975.07,4540 ; 4975.07,4540 cw(c4975.07,4575.07) 4950.27,4550.27 ccw(c4975.07,4575.07) 4975.07,4540 ; 4999.21,4540 ccw(c4999.21,4480.79) 4957.34,4522.66 cw(c4999.21,4480.79) 4999.21,4540 ; 4999.21,4540 cw(c4999.21,4599.21) 4957.34,4557.34 ccw(c4999.21,4599.21) 4999.21,4540
PB12: P1.5 R18.2 U4.73 | length 2535.8
  Top Layer w10: U4.73@5896.04,6343.28 5918.32,6321 5929.88,6321 6443.88,6835 P1.5@6930,6835 6953.33,6835 6994.36,6876.03 ; P1.5@6918.62,6845.49 cw(c6950.63,6815.98) 6948.86,6859.48 ; P1.5@6925.98,6838.71 cw(c6975.74,6792.84) 6972.99,6860.46 ; R18.2@7407.5,6850.06 7351.94,6850.06 7325.97,6876.03 6994.36,6876.03 ; 6870.79,6835 ccw(c6870.79,6894.21) 6912.66,6852.34 cw(c6870.79,6894.21) 6870.79,6835 ; 6870.79,6835 cw(c6870.79,6775.79) 6912.66,6817.66 ccw(c6870.79,6775.79) 6870.79,6835 ; 6894.93,6835 ccw(c6894.93,6870.07) 6919.73,6845.27 cw(c6894.93,6870.07) 6894.93,6835 ; 6894.93,6835 cw(c6894.93,6799.93) 6919.73,6824.73 ccw(c6894.93,6799.93) 6894.93,6835 ; 6994.36,6876.03 cw(c6949.34,6921.04) 6935.38,6858.93 ccw(c6949.34,6921.04) 6994.36,6876.03 ; 7383.36,6850.06 ccw(c7383.36,6874.21) 7400.43,6857.14 cw(c7383.36,6874.21) 7383.36,6850.06 ; 7383.36,6850.06 cw(c7383.36,6825.92) 7400.43,6842.99 ccw(c7383.36,6825.92) 7383.36,6850.06 ; P1.5@6930.99,6839.42 ccw(c6939.91,6879.1) 6968.67,6850.34 cw(c6939.91,6879.1) P1.5@6930.99,6839.42 ; P1.5@6933.19,6849.17 ccw(c6944.63,6900.07) 6981.52,6863.18 cw(c6944.63,6900.07) P1.5@6933.19,6849.17
PB13: P1.4 U4.74 | length 1863.6
  Top Layer w10: U4.74@5882.12,6329.37 5858.4,6353.09 5858.4,6394.99 6353.41,6890 6985,6890 P1.4@7030,6935 ; 6999.48,6912.65 cw(c7036.61,6902.7) P1.4@7028.9,6940.36 ; 7007.65,6904.48 ccw(c6997.7,6941.61) P1.4@7035.36,6933.9 ; 6988.13,6893.13 ccw(c6946.26,6935) 7005.47,6935 cw(c6946.26,6935) 6988.13,6893.13 ; 6988.13,6893.13 cw(c7030,6851.26) 7030,6910.47 ccw(c7030,6851.26) 6988.13,6893.13 ; 7005.2,6910.2 ccw(c6980.4,6935) 7015.47,6935 cw(c6980.4,6935) 7005.2,6910.2 ; 7005.2,6910.2 cw(c7030,6885.4) 7030,6920.47 ccw(c7030,6885.4) 7005.2,6910.2 ; 5858.4,6355.78 ccw(c5865.75,6355.78) 5860.55,6350.58 cw(c5865.75,6355.78) 5858.4,6355.78
PB14: P1.3 U4.75 | length 1743.5
  Top Layer w10: U4.75@5868.2,6315.45 5841.9,6341.75 ; P1.3@6930,6935 6375.07,6935 5841.9,6401.83 5841.9,6341.75 ; 5841.9,6341.75 ccw(c5847.07,6341.75) 5846.8,6336.59 cw(c5847.07,6341.75) 5841.9,6341.75 ; 6870.79,6935 ccw(c6870.79,6994.21) 6912.66,6952.34 cw(c6870.79,6994.21) 6870.79,6935 ; 6870.79,6935 cw(c6870.79,6875.79) 6912.66,6917.66 ccw(c6870.79,6875.79) 6870.79,6935 ; 6894.93,6935 ccw(c6894.93,6970.07) 6919.73,6945.27 cw(c6894.93,6970.07) 6894.93,6935 ; 6894.93,6935 cw(c6894.93,6899.93) 6919.73,6924.73 ccw(c6894.93,6899.93) 6894.93,6935 ; 5841.9,6348.09 ccw(c5858.06,6348.09) 5846.63,6336.66 cw(c5858.06,6348.09) 5841.9,6348.09
PB15: P1.2 U4.76 | length 1964.5
  Top Layer w10: U4.76@5854.28,6301.53 5825.4,6330.41 5825.4,6408.66 6392.76,6976.03 6971.03,6976.03 P1.2@7030,7035 ; 6999.48,7012.65 cw(c7036.61,7002.7) P1.2@7028.9,7040.36 ; 7007.65,7004.48 ccw(c6997.7,7041.61) P1.2@7035.36,7033.9 ; 6988.13,6993.13 ccw(c6946.26,7035) 7005.47,7035 cw(c6946.26,7035) 6988.13,6993.13 ; 6988.13,6993.13 cw(c7030,6951.26) 7030,7010.47 ccw(c7030,6951.26) 6988.13,6993.13 ; 7005.2,7010.2 ccw(c6980.4,7035) 7015.47,7035 cw(c6980.4,7035) 7005.2,7010.2 ; 7005.2,7010.2 cw(c7030,6985.4) 7030,7020.47 ccw(c7030,6985.4) 7005.2,7010.2
PC0: P1.39 P6.3 U4.26 | length 3517.5
  Top Layer w10: U4.26@6383.22,5577.72 6825.94,5135 P1.39@6930,5135 6971.03,5176.03 ; P1.39@6924.67,5136.26 cw(c6962.93,5127.2) 6953.31,5165.32 ; P1.39@6931.26,5129.67 ccw(c6922.2,5167.93) 6960.32,5158.31 ; 7409.48,6582.65 cw(c7446.61,6572.7) P6.3@7438.9,6610.36 ; 7417.65,6574.48 ccw(c7407.7,6611.61) P6.3@7445.36,6603.9 ; P6.3@7440,6605 7315,6480 7315,6300 7090,6075 7090,5200 7066.03,5176.03 6971.03,5176.03 ; 6870.79,5135 ccw(c6870.79,5194.21) 6912.66,5152.34 cw(c6870.79,5194.21) 6870.79,5135 ; 6870.79,5135 cw(c6870.79,5075.79) 6912.66,5117.66 ccw(c6870.79,5075.79) 6870.79,5135 ; 6894.93,5135 ccw(c6894.93,5170.07) 6919.73,5145.27 cw(c6894.93,5170.07) 6894.93,5135 ; 6894.93,5135 cw(c6894.93,5099.93) 6919.73,5124.73 ccw(c6894.93,5099.93) 6894.93,5135 ; 6954.3,5159.3 ccw(c6977.9,5135.7) 6944.53,5135.21 cw(c6977.9,5135.7) 6954.3,5159.3 ; 6954.3,5159.3 cw(c6930.7,5182.9) 6930.21,5149.53 ccw(c6930.7,5182.9) 6954.3,5159.3 ; 6971.03,5176.03 ccw(c7010.87,5136.18) 6954.52,5135.36 cw(c7010.87,5136.18) 6971.03,5176.03 ; 6971.03,5176.03 cw(c6931.18,5215.87) 6930.36,5159.52 ccw(c6931.18,5215.87) 6971.03,5176.03 ; 7398.13,6563.13 ccw(c7356.26,6605) 7415.47,6605 cw(c7356.26,6605) 7398.13,6563.13 ; 7398.13,6563.13 cw(c7440,6521.26) 7440,6580.47 ccw(c7440,6521.26) 7398.13,6563.13 ; 7415.2,6580.2 ccw(c7390.4,6605) 7425.47,6605 cw(c7390.4,6605) 7415.2,6580.2 ; 7415.2,6580.2 cw(c7440,6555.4) 7440,6590.47 ccw(c7440,6555.4) 7415.2,6580.2
PC1: P1.38 P6.4 U4.27 | length 3649.5
  Top Layer w10: U4.27@6397.14,5591.64 6794.8,5193.97 6988.97,5193.97 ; 6999.68,5211.69 cw(c7037.8,5202.07) P1.38@7028.74,5240.33 ; 7006.69,5204.68 ccw(c6997.07,5242.8) P1.38@7035.33,5233.74 ; P1.38@7024.64,5236.1 cw(c7062.3,5228.39) 7052.35,5265.52 ; P1.38@7031.1,5229.64 ccw(c7023.39,5267.3) 7060.52,5257.35 ; 7509.68,6628.31 ccw(c7547.8,6637.93) P6.4@7538.74,6599.67 ; 7516.69,6635.32 cw(c7507.07,6597.2) P6.4@7545.33,6606.26 ; P6.4@7540,6605 7498.97,6646.03 ; 6988.97,5193.97 ccw(c6949.13,5233.82) 7005.48,5234.64 cw(c6949.13,5233.82) 6988.97,5193.97 ; 6988.97,5193.97 cw(c7028.82,5154.13) 7029.64,5210.48 ccw(c7028.82,5154.13) 6988.97,5193.97 ; 6988.97,5193.97 P1.38@7030,5235 7073.5,5278.5 7073.5,6081.83 7298.5,6306.83 7298.5,6521.52 7423.01,6646.03 7498.97,6646.03 ; 7005.7,5210.7 ccw(c6982.1,5234.3) 7015.47,5234.79 cw(c6982.1,5234.3) 7005.7,5210.7 ; 7005.7,5210.7 cw(c7029.3,5187.1) 7029.79,5220.47 ccw(c7029.3,5187.1) 7005.7,5210.7 ; 7054.8,5259.8 ccw(c7079.6,5235) 7044.53,5235 cw(c7079.6,5235) 7054.8,5259.8 ; 7054.8,5259.8 cw(c7030,5284.6) 7030,5249.53 ccw(c7030,5284.6) 7054.8,5259.8 ; 7071.87,5276.87 ccw(c7113.74,5235) 7054.53,5235 cw(c7113.74,5235) 7071.87,5276.87 ; 7071.87,5276.87 cw(c7030,5318.74) 7030,5259.53 ccw(c7030,5318.74) 7071.87,5276.87 ; 7498.97,6646.03 ccw(c7538.82,6685.87) 7539.64,6629.52 cw(c7538.82,6685.87) 7498.97,6646.03 ; 7498.97,6646.03 cw(c7459.13,6606.18) 7515.48,6605.36 ccw(c7459.13,6606.18) 7498.97,6646.03 ; 7515.7,6629.3 ccw(c7539.3,6652.9) 7539.79,6619.53 cw(c7539.3,6652.9) 7515.7,6629.3 ; 7515.7,6629.3 cw(c7492.1,6605.7) 7525.47,6605.21 ccw(c7492.1,6605.7) 7515.7,6629.3
PC2: P1.37 U4.28 | length 968.6
  Top Layer w10: U4.28@6411.06,5605.56 6781.61,5235 P1.37@6930,5235 ; 6870.79,5235 ccw(c6870.79,5294.21) 6912.66,5252.34 cw(c6870.79,5294.21) 6870.79,5235 ; 6870.79,5235 cw(c6870.79,5175.79) 6912.66,5217.66 ccw(c6870.79,5175.79) 6870.79,5235 ; 6894.93,5235 ccw(c6894.93,5270.07) 6919.73,5245.27 cw(c6894.93,5270.07) 6894.93,5235 ; 6894.93,5235 cw(c6894.93,5199.93) 6919.73,5224.73 ccw(c6894.93,5199.93) 6894.93,5235
PC3: P1.36 U4.29 | length 1129.8
  Top Layer w10: U4.29@6424.98,5619.48 6750.48,5293.97 6988.97,5293.97 ; 6999.68,5311.69 cw(c7037.8,5302.07) P1.36@7028.74,5340.33 ; 7006.69,5304.68 ccw(c6997.07,5342.8) P1.36@7035.33,5333.74 ; P1.36@7030,5335 6988.97,5293.97 ; 6988.97,5293.97 ccw(c6949.13,5333.82) 7005.48,5334.64 cw(c6949.13,5333.82) 6988.97,5293.97 ; 6988.97,5293.97 cw(c7028.82,5254.13) 7029.64,5310.48 ccw(c7028.82,5254.13) 6988.97,5293.97 ; 7005.7,5310.7 ccw(c6982.1,5334.3) 7015.47,5334.79 cw(c6982.1,5334.3) 7005.7,5310.7 ; 7005.7,5310.7 cw(c7029.3,5287.1) 7029.79,5320.47 ccw(c7029.3,5287.1) 7005.7,5310.7
PC4: P1.27 U4.44 | length 1005.1
  Top Layer w10: U4.44@6424.98,5953.54 6459.02,5987.58 6677.42,5987.58 P1.27@6930,5735 ; 6899.48,5757.35 ccw(c6936.61,5767.3) P1.27@6928.9,5729.64 ; 6907.65,5765.52 cw(c6897.7,5728.39) P1.27@6935.36,5736.1 ; 6888.13,5776.87 ccw(c6930,5818.74) 6930,5759.53 cw(c6930,5818.74) 6888.13,5776.87 ; 6888.13,5776.87 cw(c6846.26,5735) 6905.47,5735 ccw(c6846.26,5735) 6888.13,5776.87 ; 6905.2,5759.8 ccw(c6930,5784.6) 6930,5749.53 cw(c6930,5784.6) 6905.2,5759.8 ; 6905.2,5759.8 cw(c6880.4,5735) 6915.47,5735 ccw(c6880.4,5735) 6905.2,5759.8
PC5: P1.26 U4.45 | length 1111
  Top Layer w10: U4.45@6411.06,5967.46 6447.68,6004.08 6684.25,6004.08 6894.36,5793.97 6988.97,5793.97 ; 6999.68,5811.69 cw(c7037.8,5802.07) P1.26@7028.74,5840.33 ; 7006.69,5804.68 ccw(c6997.07,5842.8) P1.26@7035.33,5833.74 ; P1.26@7030,5835 6988.97,5793.97 ; 6988.97,5793.97 ccw(c6949.13,5833.82) 7005.48,5834.64 cw(c6949.13,5833.82) 6988.97,5793.97 ; 6988.97,5793.97 cw(c7028.82,5754.13) 7029.64,5810.48 ccw(c7028.82,5754.13) 6988.97,5793.97 ; 7005.7,5810.7 ccw(c6982.1,5834.3) 7015.47,5834.79 cw(c6982.1,5834.3) 7005.7,5810.7 ; 7005.7,5810.7 cw(c7029.3,5787.1) 7029.79,5820.47 ccw(c7029.3,5787.1) 7005.7,5810.7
